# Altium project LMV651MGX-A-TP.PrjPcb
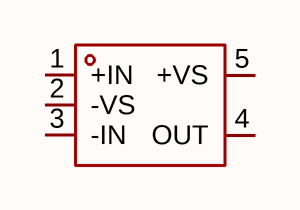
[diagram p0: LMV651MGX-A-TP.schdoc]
1 sheet, 1 parts. Net scope: global (net labels, ports and power ports of the same name join across sheets).

## Sheet LMV651MGX-A-TP.schdoc
size 127 x 101 mm

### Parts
U?  lmv651mgx-a-tp  [SOT-23-5_L2.9-W1.6-P0.95-LS2.8-BL]  (value not drawn)

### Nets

Not connected (* = marked no-connect by the designer): U? 1(+IN) 2(-VS) 3(-IN) 4(OUT) 5(+VS)

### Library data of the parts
U? = lmv651mgx-a-tp: Manufacturer: TECH PUBLIC(台舟); AddInBom: yes; ModelId: 018c57e721114987ae90467fe9f1d259; ModelTransform: 114.96,110.236,0,0,0,0,0,0,0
